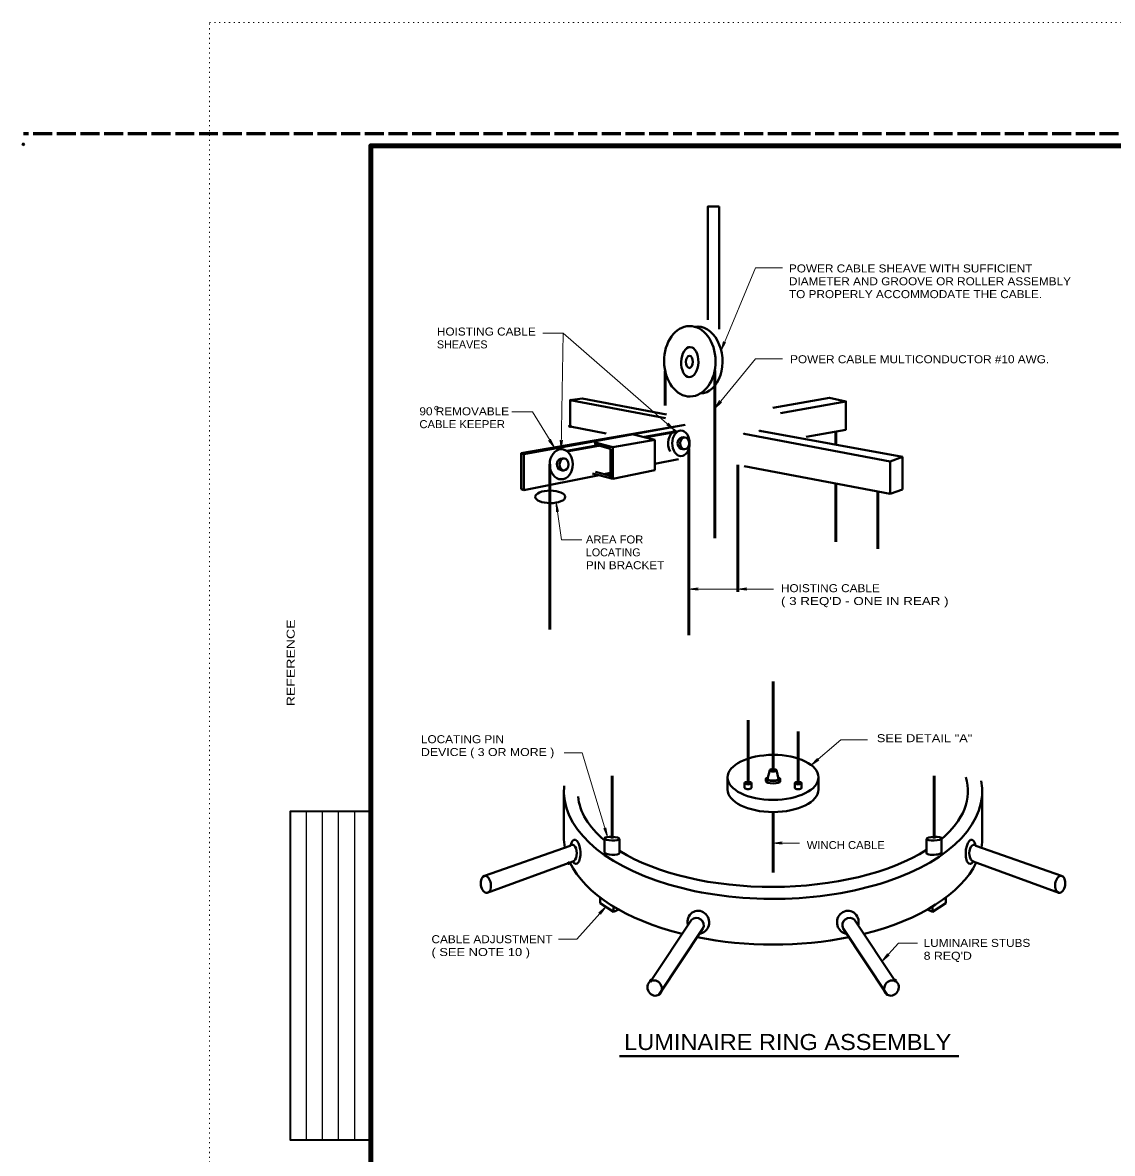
# Model space of a CAD drawing. Extents: x 312583 to 312854, y 144419 to 144597.
# Drawn here: x 312583.5 to 312686.9, y 144489.4 to 144596.8 of the extents above; entities that cross this region are included whole.
import ezdxf
from ezdxf.enums import TextEntityAlignment as Align

# ---------------------------------------------------------------- set-up
doc = ezdxf.new("R2010")
doc.units = 0
doc.header["$LTSCALE"] = 0.3
doc.header["$PDMODE"] = 32
doc.header["$PDSIZE"] = 0.15
doc.linetypes.add('DOTTED', pattern=[1.5, 0.3, -1.2])
doc.linetypes.add('LONG_DASHED', pattern=[7.5, 6, -1.5])
for name, color, linetype, lineweight in [('1', 7, 'Continuous', 40), ('2', 7, 'Continuous', 13), ('62', 7, 'DOTTED', 13), ('63', 7, 'LONG_DASHED', 60)]:
    doc.layers.add(name, color=color, linetype=linetype, lineweight=lineweight)
doc.layers.add('5', color=7, linetype='Continuous')

msp = doc.modelspace()

# ---------------------------------------------------------------- linework, layer by layer
at = {"layer": '1'}
for p, q in [((312649.5929, 144567.6766), (312649.5929, 144579.3146)), ((312636.5826, 144561.0986), (312635.4249, 144560.93)), ((312635.4249, 144558.4153), (312635.4249, 144560.9376)), ((312635.4249, 144560.93), (312644.5022, 144559.2126)), ((312636.5826, 144561.0986), (312644.5866, 144559.5806)), ((312630.7942, 144555.8776), (312646.3499, 144558.5686)), ((312631.0242, 144555.7856), (312646.3499, 144558.5686)), ((312635.4249, 144558.4153), (312638.8596, 144557.7713)), ((312641.4586, 144557.6793), (312643.4749, 144557.1503)), ((312651.9696, 144557.7253), (312665.8309, 144555.1033)), ((312666.9886, 144555.548), (312653.4492, 144558.009)), ((312661.6142, 144558.101), (312657.8576, 144557.434)), ((312637.7939, 144556.7056), (312637.7939, 144556.928)), ((312637.7939, 144556.7056), (312639.2736, 144556.3146)), ((312637.8246, 144556.9126), (312639.4959, 144556.468)), ((312639.4959, 144556.468), (312643.4749, 144557.1503)), ((312643.4749, 144557.1503), (312643.4749, 144554.283)), ((312630.7942, 144552.4736), (312630.7942, 144555.8776)), ((312631.0242, 144555.7856), (312630.7942, 144555.8776)), ((312631.0242, 144552.3816), (312631.0242, 144555.7856)), ((312639.2736, 144556.3146), (312639.2736, 144553.5853)), ((312639.4959, 144556.468), (312639.4959, 144553.4626)), ((312665.8309, 144555.1033), (312666.9962, 144555.5326)), ((312666.9886, 144555.5326), (312666.9886, 144552.443)), ((312643.4749, 144554.8733), (312645.7366, 144555.318)), ((312651.9696, 144554.651), (312665.8309, 144552.029)), ((312665.8309, 144555.1033), (312665.8309, 144552.029)), ((312631.0242, 144552.3816), (312638.1926, 144553.8076)), ((312637.5716, 144553.9763), (312639.4959, 144553.4626)), ((312637.8552, 144554.1143), (312639.2736, 144553.7386)), ((312638.6449, 144553.9073), (312639.2736, 144554.03)), ((312639.4959, 144553.4626), (312643.4749, 144554.283)), ((312631.0242, 144552.3816), (312630.7942, 144552.4736)), ((312665.8309, 144552.029), (312666.9886, 144552.4506)), ((312654.3776, 144525.7731), (312654.1782, 144524.9528)), ((312655.0139, 144525.7731), (312655.2209, 144524.9528)), ((312650.3832, 144525.0984), (312650.3832, 144523.9408)), ((312652.0009, 144524.5541), (312652.0009, 144524.1018)), ((312652.6372, 144524.5541), (312652.6372, 144524.1018)), ((312654.0096, 144524.9528), (312654.0096, 144524.7304)), ((312655.3896, 144524.9528), (312655.3896, 144524.7304)), ((312656.7619, 144524.5541), (312656.7619, 144524.1018)), ((312657.3982, 144524.5541), (312657.3982, 144524.1018)), ((312659.0159, 144525.1061), (312659.0159, 144523.9484)), ((312634.8352, 144523.7951), (312634.8352, 144519.4558)), ((312674.5639, 144523.7951), (312674.5639, 144519.4558)), ((312638.6992, 144517.9608), (312638.6992, 144519.3101)), ((312640.1176, 144517.8918), (312640.1176, 144519.2411)), ((312669.2816, 144517.8918), (312669.2816, 144519.2411)), ((312670.6999, 144517.9608), (312670.6999, 144519.3101)), ((312635.4486, 144518.6124), (312627.3142, 144515.7451)), ((312673.9506, 144518.6124), (312682.0849, 144515.7451)), ((312635.6862, 144517.1021), (312627.5596, 144514.1274)), ((312673.7129, 144517.1021), (312681.8396, 144514.1274)), ((312638.2852, 144513.1538), (312638.2852, 144513.6904)), ((312671.1139, 144513.1538), (312671.1139, 144513.6904)), ((312639.5656, 144512.3258), (312638.2852, 144513.1538)), ((312639.5656, 144512.3258), (312639.5656, 144512.8241)), ((312639.5656, 144512.3258), (312640.0409, 144512.5481)), ((312669.8336, 144512.3258), (312669.3582, 144512.5481)), ((312669.8336, 144512.3258), (312671.1139, 144513.1538)), ((312669.8336, 144512.3258), (312669.8336, 144512.8241)), ((312643.0692, 144505.7248), (312646.9639, 144511.5744)), ((312666.3299, 144505.7248), (312662.4352, 144511.5744)), ((312643.8666, 144504.4598), (312648.0449, 144510.7464)), ((312665.5326, 144504.4598), (312661.3542, 144510.7464))]:
    msp.add_line(p, q, dxfattribs=at)
at = {"layer": '1', "lineweight": 53}
for p, q in [((312644.4562, 144563.7053), (312644.4562, 144560.4163)), ((312649.1559, 144563.7283), (312649.1559, 144547.8123)), ((312642.5089, 144557.4033), (312645.5679, 144557.94)), ((312660.6636, 144556.698), (312660.6636, 144557.9323)), ((312635.1106, 144556.0846), (312638.1236, 144556.6213)), ((312646.7102, 144556.3376), (312646.7102, 144538.62)), ((312633.4929, 144554.835), (312633.4929, 144539.1566)), ((312651.3562, 144554.7966), (312651.3562, 144542.714)), ((312660.6636, 144553.0026), (312660.6636, 144547.475)), ((312664.6426, 144552.2513), (312664.6426, 144546.808)), ((312654.6996, 144534.2064), (312654.6996, 144525.6581)), ((312652.3229, 144530.5264), (312652.3229, 144524.5541)), ((312657.0839, 144529.4531), (312657.0839, 144524.5541)), ((312639.4122, 144525.2518), (312639.4122, 144519.2794)), ((312669.9869, 144525.2518), (312669.9869, 144519.2794)), ((312654.6996, 144521.8094), (312654.6996, 144516.0748))]:
    msp.add_line(p, q, dxfattribs=at)
at = {"layer": '1', "lineweight": 25}
for p, q in [((312610.4087, 144490.6573), (312610.4087, 144521.8756)), ((312611.9315, 144490.6573), (312611.9315, 144521.8756)), ((312613.4543, 144490.6573), (312613.4543, 144521.8756)), ((312614.9772, 144490.6573), (312614.9772, 144521.8756))]:
    msp.add_line(p, q, dxfattribs=at)
at = {"layer": '1', "lineweight": 158}
msp.add_lwpolyline([(312616.5, 144423.1446), (312616.5, 144585.0846), (312849, 144585.0846)], dxfattribs=at)
at = {"layer": '1'}
for points in [[(312648.5042, 144568.543), (312648.5042, 144579.3146), (312649.5929, 144579.3146)], [(312661.6142, 144560.8073), (312660.0502, 144561.1523), (312654.6836, 144560.194)], [(312661.6142, 144558.101), (312661.6142, 144560.8073), (312655.4042, 144559.7033)]]:
    msp.add_lwpolyline(points, dxfattribs=at)
at = {"layer": '1', "lineweight": 35}
msp.add_lwpolyline([(312616.5, 144490.6573), (312608.8858, 144490.6573), (312608.8858, 144521.8756), (312616.5, 144521.8756)], dxfattribs=at)
at = {"layer": '1'}
for centre, radius, start, end in [((312646.3695, 144556.8147), 1.6404, 126.5979, 207.62913), ((312646.196, 144556.8344), 0.5746, 77.61479, 280.04693), ((312634.742, 144554.8257), 0.5746, 77.61479, 280.04693), ((312647.418, 144511.0581), 0.6978, 333.56276, 132.27946), ((312661.9811, 144511.0581), 0.6978, 47.72054, 206.43724)]:
    msp.add_arc(centre, radius, start, end, dxfattribs=at)
for centre, major_axis, ratio in [((312646.7984, 144564.6215), (-0.0422, 3.3465), 0.729358), ((312646.7907, 144564.5448), (0.0498, 1.4298), 0.57002), ((312646.7524, 144564.5601), (0.0038, 0.5865), 0.54533), ((312645.9512, 144556.8283), (0, 1.219), 0.680109), ((312646.3077, 144556.8321), (0.0115, 0.5635), 0.745224), ((312634.5892, 144554.835), (0, 1.426), 0.767456), ((312634.8537, 144554.8235), (0.0115, 0.5635), 0.745224), ((312633.5427, 144551.7415), (-1.4298, 0.0038), 0.415614), ((312654.6996, 144525.1023), (-4.3163, -0.0038), 0.494672), ((312654.6957, 144525.7731), (-0.3182, 0), 0.361472), ((312652.3191, 144524.5541), (0.3182, 0), 0.361472), ((312657.0801, 144524.5541), (-0.3182, 0), 0.361472), ((312639.4084, 144519.2756), (-0.7092, 0.0345), 0.253232), ((312669.9907, 144519.2756), (0.7092, 0.0345), 0.253232), ((312627.4369, 144514.9363), (-0.1227, 0.8088), 0.583076), ((312681.9622, 144514.9363), (0.1227, 0.8088), 0.583076), ((312643.4564, 144505.0923), (0.4102, -0.6325), 0.877329), ((312665.9427, 144505.0923), (-0.4102, -0.6325), 0.877329)]:
    msp.add_ellipse(centre, major_axis=major_axis, ratio=ratio, dxfattribs=at)
for centre, major_axis, ratio, start_param, end_param in [((312647.6341, 144564.7403), (0.2338, -3.1817), 0.708049, 6.2504694, 9.48822718), ((312654.6996, 144523.7951), (-19.8643, 0), 0.515245, 6.23522647, 9.52118205), ((312654.6996, 144524.9528), (-0.69, 0), 0.288889, 5.51118463, 10.21488808), ((312654.6996, 144524.7304), (-0.69, 0), 0.288889, 6.28318531, 9.42477796), ((312654.6996, 144524.9528), (-0.5175, 0), 0.288889, 6.28318531, 9.42477796), ((312654.6804, 144523.7338), (-18.5112, -0.0613), 0.488373, 2.61511714, 3.28802612), ((312654.6804, 144523.7338), (-18.5112, -0.0613), 0.488373, 0.04241436, 0.5273572), ((312654.6996, 144523.9446), (-4.3163, -0.0038), 0.494672, 6.28318531, 9.42477796), ((312652.3191, 144524.1018), (0.3182, 0), 0.361472, 3.14159265, 6.28318531), ((312657.0801, 144524.1018), (-0.3182, 0), 0.361472, 6.28318531, 9.42477796), ((312654.6996, 144519.4558), (-19.8643, 0), 0.515245, 6.28318531, 6.38343847), ((312635.9225, 144518.0216), (0.0838, -1.1493), 0.417624, 5.60537506, 10.41594065), ((312673.4766, 144518.0216), (-0.0838, -1.1493), 0.417624, 2.15042996, 6.96099556), ((312654.6991, 144519.111), (-19.8613, -0.3467), 0.515245, 3.04283145, 3.14140139), ((312635.6434, 144517.9083), (-0.0033, -0.7941), 0.535851, 0.0916356, 3.62488232), ((312639.4084, 144517.9263), (-0.7092, 0.0345), 0.253232, 0, 3.14159265), ((312654.6804, 144523.7338), (-18.5112, -0.0613), 0.488373, 0.66389876, 2.4779919), ((312669.9907, 144517.9263), (0.7092, 0.0345), 0.253232, 3.14159265, 6.28318531), ((312673.7558, 144517.9083), (0.0033, -0.7941), 0.535851, 2.65830298, 6.1915497), ((312654.6996, 144519.4558), (-19.8643, 0), 0.515245, 0.24210015, 1.12156225), ((312654.6996, 144519.4558), (-19.8643, 0), 0.515245, 2.02152431, 2.89954777), ((312647.6002, 144511.3406), (0.115, -1.0848), 0.942368, 6.26367374, 11.1116798), ((312661.7989, 144511.3406), (-0.115, -1.0848), 0.942368, 1.45469082, 6.30269688), ((312654.6996, 144519.4558), (-19.8643, 0), 0.515245, 1.19960072, 1.94207343)]:
    msp.add_ellipse(centre, major_axis=major_axis, ratio=ratio, start_param=start_param, end_param=end_param, dxfattribs=at)
for p in [(312583.526, 144585.2246), (312635.4249, 144558.4613), (312635.2876, 144516.9488), (312643.0999, 144505.8014), (312666.2992, 144505.8014)]:
    msp.add_point(p, dxfattribs=at)
at = {"layer": '2'}
for p, q in [((312649.7692, 144565.6526), (312653.0352, 144573.5033)), ((312653.0352, 144573.5033), (312655.6036, 144573.5033)), ((312632.8336, 144567.301), (312634.7732, 144567.301)), ((312634.5892, 144556.261), (312634.7732, 144567.301)), ((312645.3379, 144558.0856), (312634.7732, 144567.301)), ((312649.7692, 144565.6526), (312649.9992, 144566.496)), ((312649.7692, 144565.6526), (312650.1986, 144566.4116)), ((312649.9992, 144566.496), (312649.9992, 144566.197)), ((312650.1986, 144566.4116), (312649.9992, 144566.197)), ((312649.1559, 144560.148), (312653.0352, 144564.8476)), ((312653.0352, 144564.8476), (312655.6036, 144564.8476)), ((312649.1559, 144560.148), (312649.6236, 144560.884)), ((312649.6236, 144560.884), (312649.5316, 144560.6003)), ((312629.9126, 144559.8106), (312631.8522, 144559.8106)), ((312633.9376, 144556.422), (312631.8522, 144559.8106)), ((312649.1559, 144560.148), (312649.7922, 144560.746)), ((312649.7922, 144560.746), (312649.5316, 144560.6003)), ((312644.7552, 144558.7373), (312644.8932, 144558.4766)), ((312645.3379, 144558.0856), (312644.7552, 144558.7373)), ((312644.6172, 144558.5763), (312644.8932, 144558.4766)), ((312645.3379, 144558.0856), (312644.6172, 144558.5763)), ((312633.3932, 144557.1043), (312633.6309, 144556.928)), ((312633.9376, 144556.422), (312633.3932, 144557.1043)), ((312633.5772, 144557.2193), (312633.6309, 144556.928)), ((312633.9376, 144556.422), (312633.5772, 144557.2193)), ((312634.4972, 144557.1273), (312634.5969, 144556.8513)), ((312634.5892, 144556.261), (312634.4972, 144557.1273)), ((312634.5892, 144556.261), (312634.7119, 144557.1273)), ((312634.7119, 144557.1273), (312634.5969, 144556.8513)), ((312634.6122, 144547.6666), (312634.1139, 144551.1933)), ((312634.1139, 144551.1933), (312634.1292, 144550.3193)), ((312634.1139, 144551.1933), (312634.3439, 144550.35)), ((312634.1292, 144550.3193), (312634.1982, 144550.6106)), ((312634.3439, 144550.35), (312634.1982, 144550.6106)), ((312634.6122, 144547.6666), (312636.5519, 144547.6666)), ((312646.7102, 144542.99), (312647.5766, 144543.0973)), ((312646.7102, 144542.99), (312647.5766, 144542.8826)), ((312647.5766, 144543.0973), (312647.3006, 144542.99)), ((312647.5766, 144542.8826), (312647.3006, 144542.99)), ((312651.3562, 144542.99), (312652.2226, 144543.0973)), ((312651.3562, 144542.99), (312652.2226, 144542.8826)), ((312652.2226, 144543.0973), (312651.9466, 144542.99)), ((312652.2226, 144542.8826), (312651.9466, 144542.99)), ((312661.1472, 144528.6634), (312658.3182, 144526.2638)), ((312661.1472, 144528.6634), (312663.6696, 144528.6634)), ((312634.8506, 144527.4214), (312636.5832, 144527.4214)), ((312638.9752, 144519.4404), (312636.5832, 144527.4214)), ((312658.3182, 144526.2638), (312658.9086, 144526.9078)), ((312658.3182, 144526.2638), (312659.0466, 144526.7391)), ((312658.9086, 144526.9078), (312658.7706, 144526.6471)), ((312659.0466, 144526.7391), (312658.7706, 144526.6471)), ((312638.6226, 144520.2378), (312638.8066, 144520.0078)), ((312638.9752, 144519.4404), (312638.6226, 144520.2378)), ((312638.8296, 144520.2991), (312638.8066, 144520.0078)), ((312638.9752, 144519.4404), (312638.8296, 144520.2991)), ((312654.6996, 144518.8578), (312655.5659, 144518.9651)), ((312654.6996, 144518.8578), (312657.2219, 144518.8578)), ((312654.6996, 144518.8578), (312655.5659, 144518.7504)), ((312655.5659, 144518.9651), (312655.2899, 144518.8578)), ((312655.5659, 144518.7504), (312655.2899, 144518.8578)), ((312638.8219, 144512.8088), (312636.0696, 144509.7421)), ((312638.8219, 144512.8088), (312638.1626, 144512.2338)), ((312638.8219, 144512.8088), (312638.3236, 144512.0958)), ((312638.1626, 144512.2338), (312638.4309, 144512.3718)), ((312638.3236, 144512.0958), (312638.4309, 144512.3718)), ((312634.3369, 144509.7421), (312636.0696, 144509.7421)), ((312666.6059, 144509.3511), (312665.0649, 144507.6338)), ((312666.6059, 144509.3511), (312668.3999, 144509.3511)), ((312665.0649, 144507.6338), (312665.5632, 144508.3468)), ((312665.5632, 144508.3468), (312665.4559, 144508.0708)), ((312665.0649, 144507.6338), (312665.7242, 144508.2088)), ((312665.7242, 144508.2088), (312665.4559, 144508.0708))]:
    msp.add_line(p, q, dxfattribs=at)
at = {"layer": '2', "lineweight": 40}
msp.add_line((312640.1168, 144498.6331), (312672.3456, 144498.6331), dxfattribs=at)
at = {"layer": '2'}
msp.add_lwpolyline([(312646.7102, 144542.99), (312651.3562, 144542.99), (312654.7296, 144542.99)], dxfattribs=at)
msp.add_circle((312622.7507, 144560.1709), 0.1797, dxfattribs=at)
at = {"layer": '5'}
for p in [(312635.4939, 144560.9376), (312651.9696, 144557.7253), (312653.4492, 144558.009), (312639.4959, 144556.468)]:
    msp.add_point(p, dxfattribs=at)
at = {"layer": '62'}
for p, q in [((312601.2, 144596.7846), (312853.5, 144596.7846)), ((312601.2, 144418.5846), (312601.2, 144596.7846))]:
    msp.add_line(p, q, dxfattribs=at)
at = {"layer": '63'}
msp.add_line((312851.75, 144586.2246), (312583.526, 144586.2246), dxfattribs=at)

# ---------------------------------------------------------------- texts
at = {"layer": '1', "width": 1.3}
msp.add_text('REFERENCE                                                              ', height=0.7682, rotation=90, dxfattribs=at).set_placement((312609.2854, 144531.8549))
at = {"layer": '2'}
for s, width, p in [('POWER CABLE SHEAVE WITH SUFFICIENT', 1.1, (312656.2092, 144573.0576)), ('DIAMETER AND GROOVE OR ROLLER ASSEMBLY', 1.1, (312656.2092, 144571.8376)), ('TO PROPERLY ACCOMMODATE THE CABLE.', 1.1, (312656.2092, 144570.6176)), ('HOISTING CABLE', 1.1, (312622.7863, 144567.0623)), ('90 REMOVABLE', 1.1, (312621.1211, 144559.4876)), ('CABLE KEEPER', 1.05, (312621.1211, 144558.2676)), ('AREA FOR', 1.05, (312636.9276, 144547.313)), ('PIN BRACKET', 1.1, (312636.9276, 144544.873)), ('HOISTING CABLE', 1.1, (312655.4502, 144542.69)), ("( 3 REQ'D - ONE IN REAR )", 1.25, (312655.4502, 144541.47)), ('LOCATING PIN', 1.1, (312621.2686, 144528.3458)), ('DEVICE ( 3 OR MORE )', 1.15, (312621.2686, 144527.1258)), ('CABLE ADJUSTMENT', 1.1, (312622.2707, 144509.3501)), ('LUMINAIRE STUBS', 1.1, (312668.9979, 144508.9974)), ('( SEE NOTE 10 )', 1.2, (312622.2707, 144508.1301)), ("8 REQ'D", 1.15, (312668.9979, 144507.7774))]:
    msp.add_text(s, height=0.76, dxfattribs=dict(at, width=width)).set_placement(p)
for s, p in [('SHEAVES', (312622.7863, 144565.8423)), ('LOCATING', (312636.9276, 144546.093))]:
    msp.add_text(s, height=0.76, dxfattribs=at).set_placement(p)
for s, height, width, p in [('POWER CABLE MULTICONDUCTOR #10 AWG.', 0.76, 1.1, (312668.6155, 144564.4326)), ('SEE DETAIL "A"', 0.76, 1.2, (312669.0829, 144528.4424)), ('WINCH CABLE', 0.76, 1.05, (312661.6068, 144518.2924)), ('LUMINAIRE RING ASSEMBLY', 1.52, 1.1, (312656.093, 144499.2065))]:
    msp.add_text(s, height=height, dxfattribs=dict(at, width=width)).set_placement(p, align=Align.CENTER)

doc.saveas('drawing.dxf')
